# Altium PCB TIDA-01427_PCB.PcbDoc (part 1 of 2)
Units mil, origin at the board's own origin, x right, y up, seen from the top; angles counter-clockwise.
Board outline 1968.5 x 3149.61 mil, 4 copper layers (Top Layer, GND, PWR, Bottom Layer), stack 61.6 mil thick; 174 components, 73 nets, 411 pads, 102 vias.
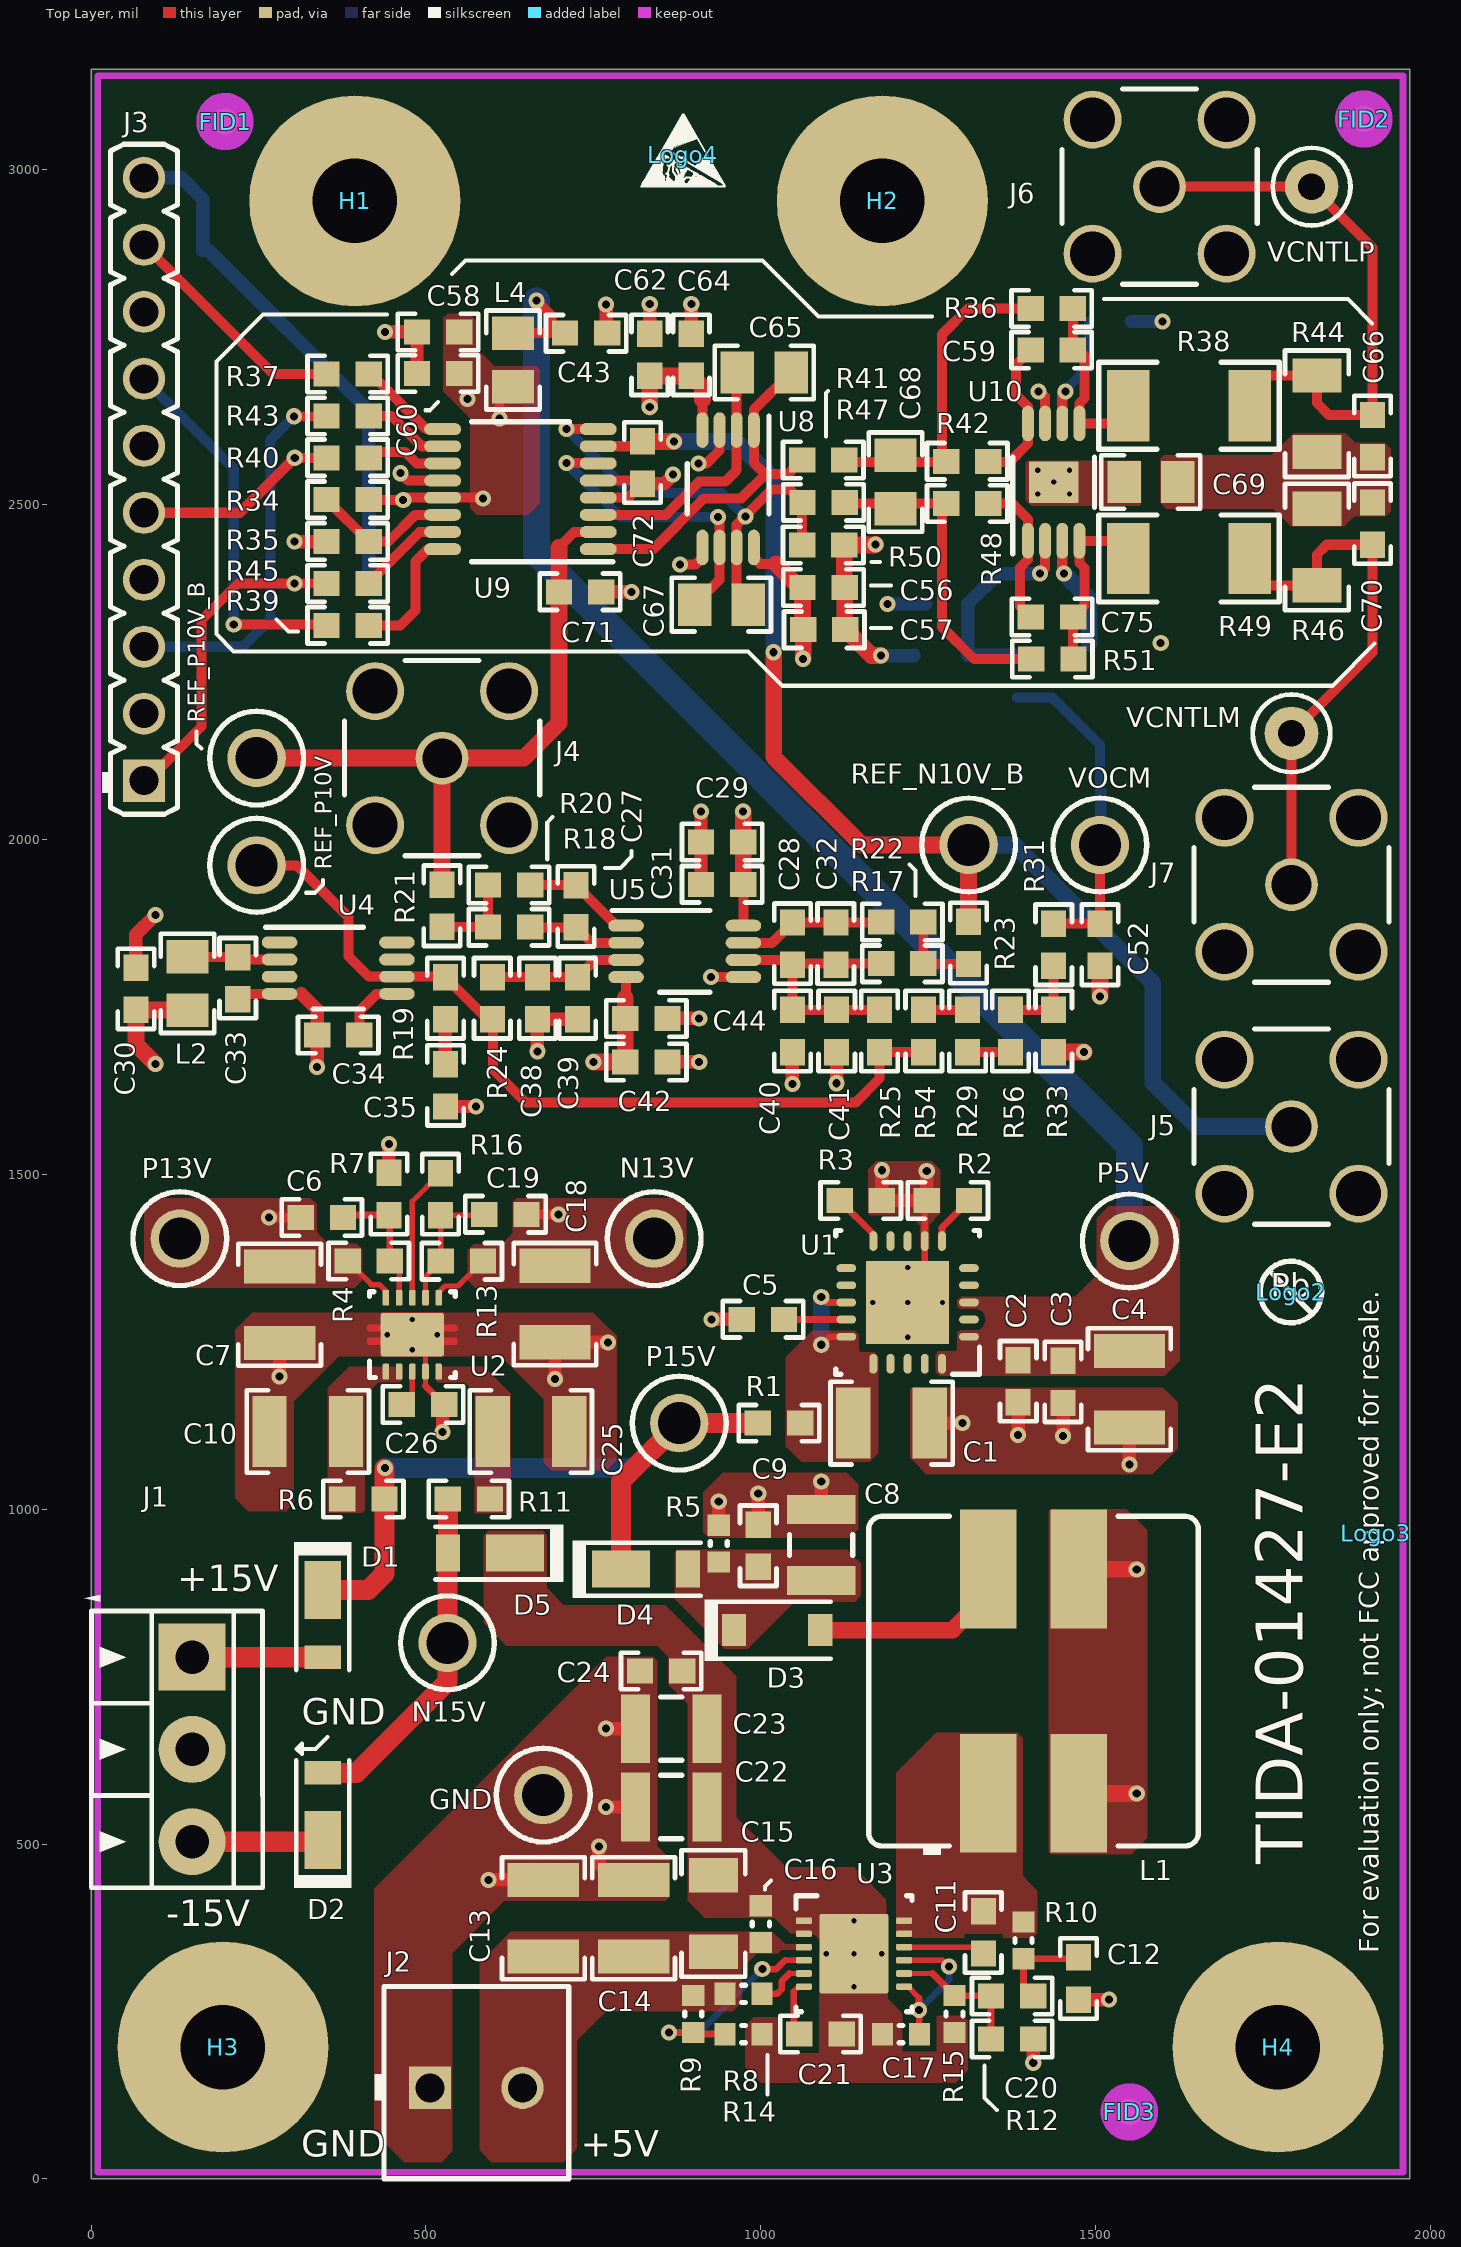
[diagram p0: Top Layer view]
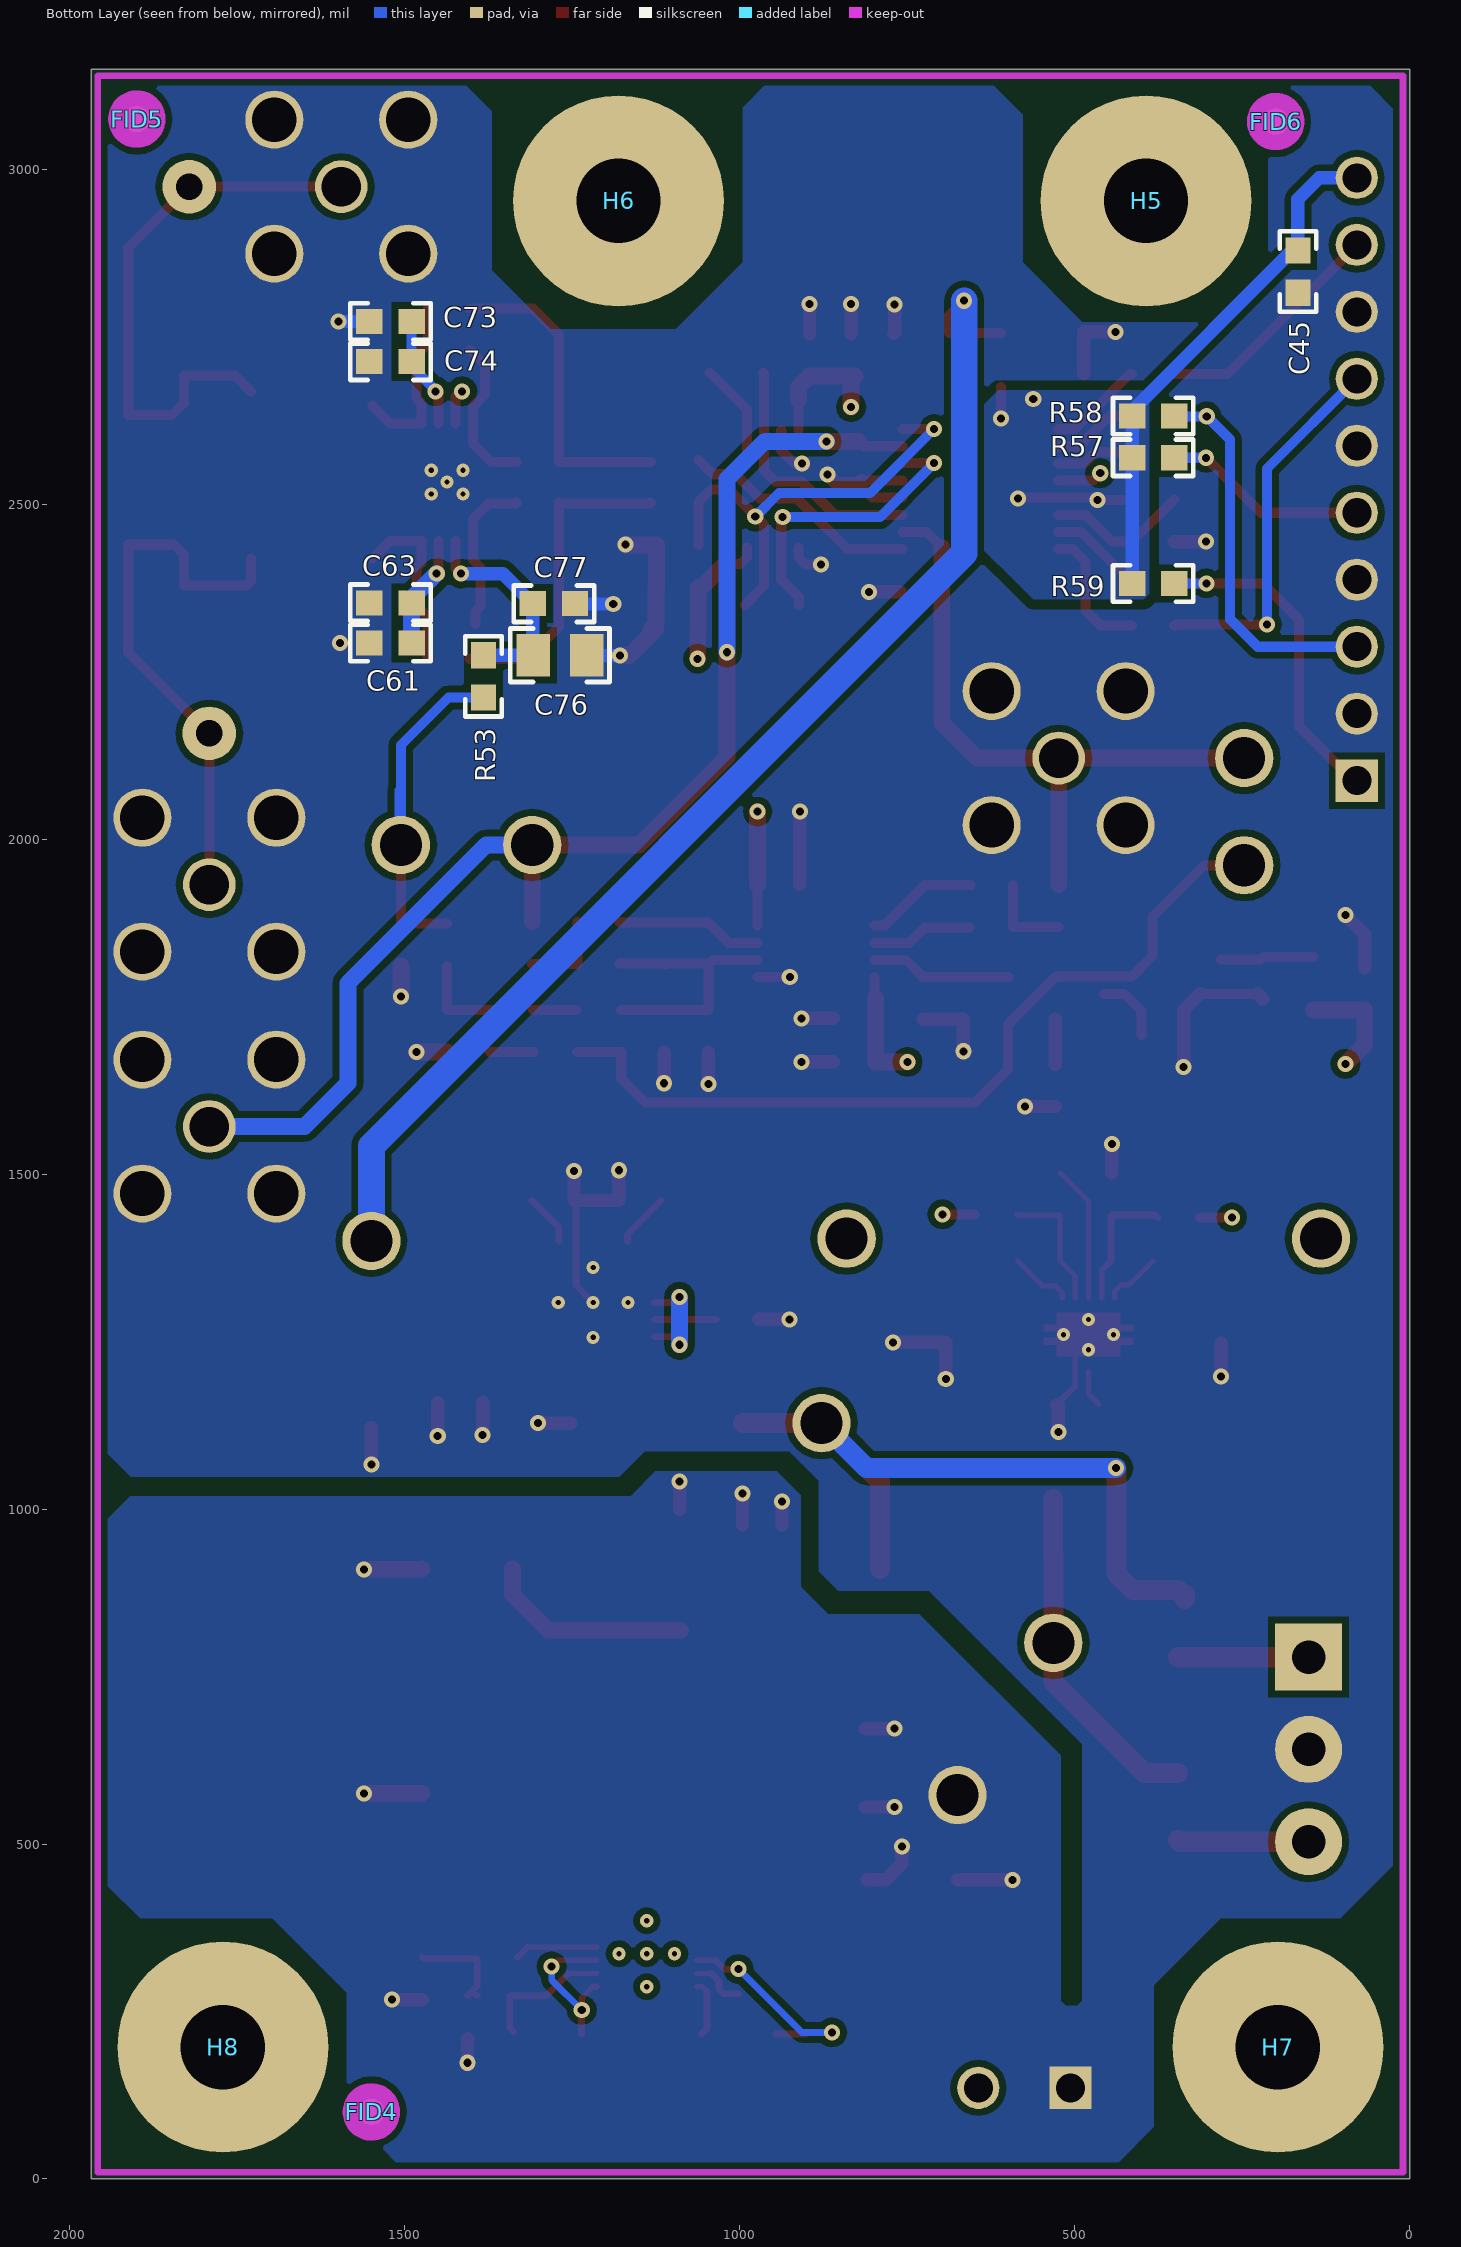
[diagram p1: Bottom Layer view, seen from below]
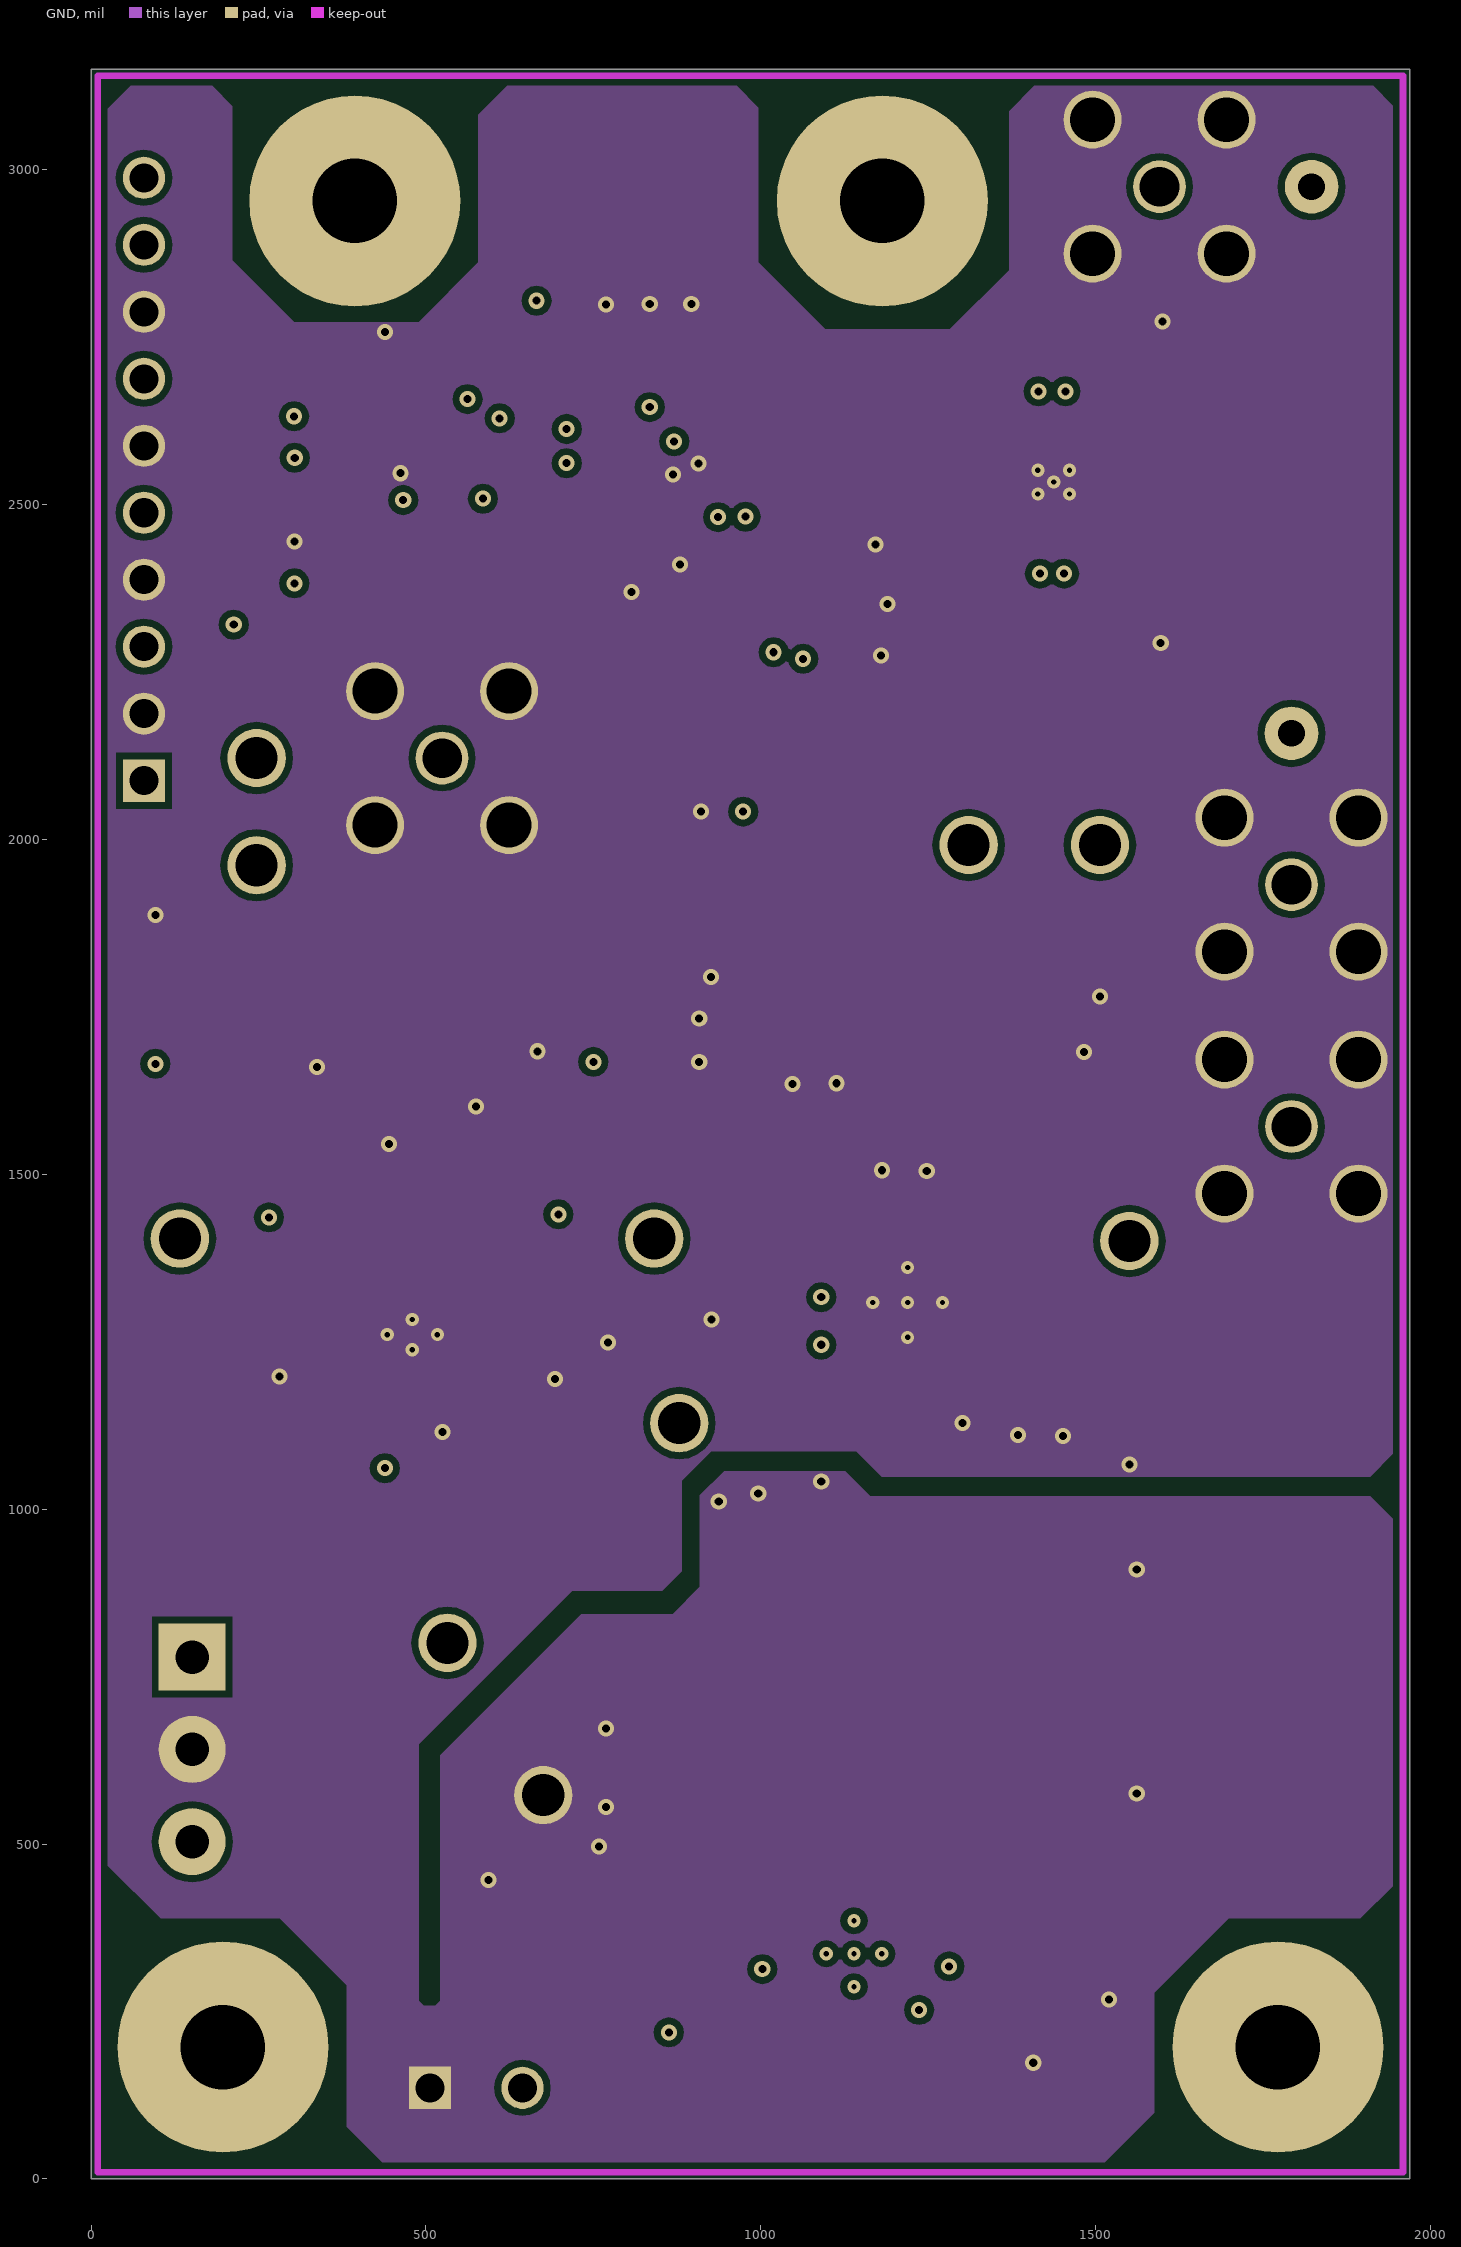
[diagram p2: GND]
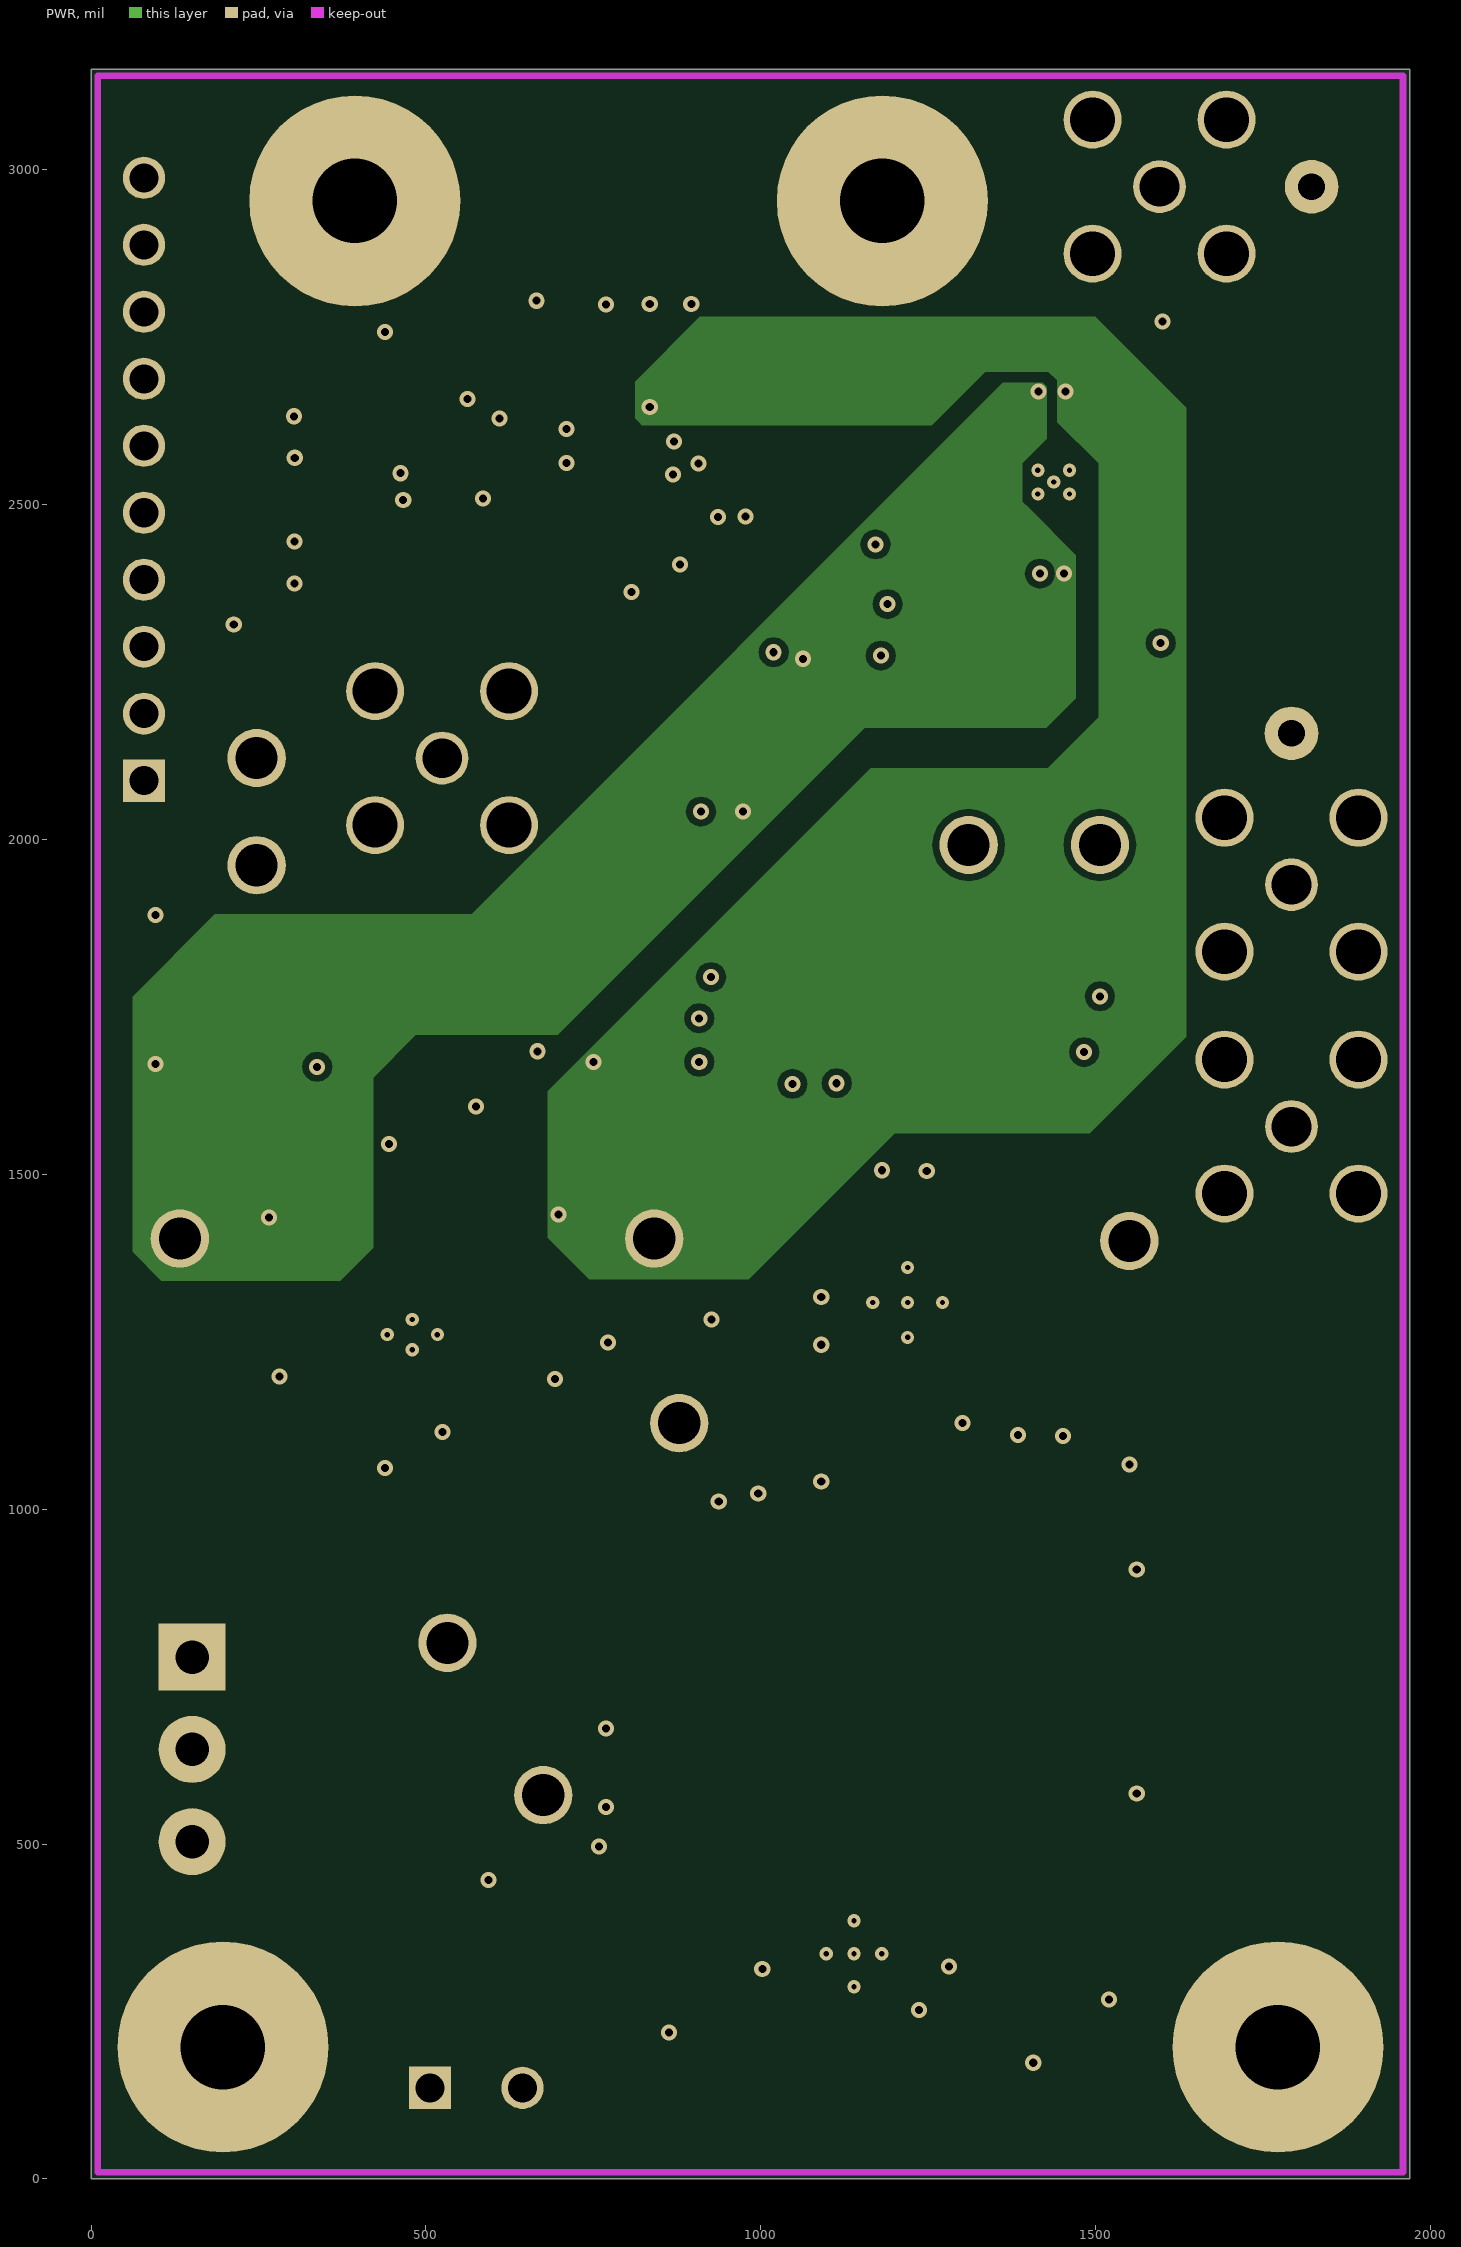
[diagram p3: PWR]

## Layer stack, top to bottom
Top Solder: solder mask 0.4, Solder Resist, Dk 3.5
Top Layer: signal copper 1.4
Dielectric 1: dielectric 10, FR-4 High Tg, Dk 4.2
GND: signal copper 1.4
Dielectric 2: dielectric 36, FR-4 High Tg, Dk 4.2
PWR: signal copper 1.4
Dielectric3: core 10, FR-4 High Tg, Dk 4.8
Bottom Layer: signal copper 1.4
Bottom Solder: solder mask 0.4, Solder Resist, Dk 3.5

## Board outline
0,0 1968.5,0 1968.5,3149.61 0,3149.61

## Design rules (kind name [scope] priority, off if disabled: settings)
AcuteAngle [All] p1: minimum=4.50000000000000E+0001 checktracksonly=FALSE
AssemblyTestPointUsage [All] p1: valid=2
Clearance Clearance_Keepouts [((IsTrack Or IsArc) And Not InPoly) And IsFree and IsKeepOut vs ((IsTrack Or IsArc) And Not InPoly) And IsFree and IsKeepOut] p1: gap=0
Clearance Clearance_Poly [InPolygon] p2: gap=10 except(15: Poly-Poly)
Clearance [All] p3: gap=7.87
ComponentClearance ComponentClearance_MountingHoles_FiducialMarks [InComponentClass('Mounting Holes') vs InComponentClass('FiducialMark')] p1: gap=10 collisioncheckmode=3 verticalgap=10 showdistances=FALSE
ComponentClearance ComponentClearance_Shunt [InComponentClass('Header') vs InComponentClass('Shunt')] p2: gap=0 collisioncheckmode=3 verticalgap=0 showdistances=FALSE
ComponentClearance ComponentClearance_Logo [InComponentClass('Logo')] p3: gap=10 collisioncheckmode=3 verticalgap=10 showdistances=FALSE
ComponentClearance ComponentClearance_ScrewToNut [(HasFootprint('NY PMS 440 0025 PH')) vs (HasFootprint('Keystone_1902C'))] p4: gap=5 collisioncheckmode=3 verticalgap=10 showdistances=FALSE
ComponentClearance ComponentClearance_MountingHoles [InComponentClass('Mounting Holes')] p5: gap=10 collisioncheckmode=3 verticalgap=100000 showdistances=FALSE
ComponentClearance ComponentClearance_SmallPassives [HasFootprint('0201*') or HasFootprint('0402*') or HasFootprint('0508') or HasFootprint('0603*') or HasFootprint('0612') or HasFootprint('0805*') or HasFootprint('0815*') or HasFootprint('0830*') or HasFootprint('1206*') or HasFootprint('1210*') or HasFootprint('1808*') or HasFootprint('1812*') or HasFootprint('1825*') or HasFootprint('2010*') or HasFootprint('2220*') or HasFootprint('2225*') or HasFootprint('2512*') or HasFootprint('2728*') or HasFootprint('3518*') vs HasFootprint('0201*') or HasFootprint('0402*') or HasFootprint('0508') or HasFootprint('0603*') or HasFootprint('0612') or HasFootprint('0805*') or HasFootprint('0815*') or HasFootprint('0830*') or HasFootprint('1206*') or HasFootprint('1210*') or HasFootprint('1808*') or HasFootprint('1812*') or HasFootprint('1825*') or HasFootprint('2010*') or HasFootprint('2220*') or HasFootprint('2225*') or HasFootprint('2512*') or HasFootprint('2728*') or HasFootprint('3518*')] p6: gap=10 collisioncheckmode=3 verticalgap=10 showdistances=FALSE
ComponentClearance ComponentClearance_THtoSMT [IsThruComponent vs IsSMTComponent] p7: gap=10 collisioncheckmode=3 verticalgap=10 showdistances=FALSE
ComponentClearance ComponentClearance_THtoTH [IsThruComponent vs IsThruComponent] p8: gap=10 collisioncheckmode=3 verticalgap=10 showdistances=FALSE
ComponentClearance [All] p9: gap=10 collisioncheckmode=3 verticalgap=10 showdistances=FALSE
DiffPairsRouting [All] p1: maxlimit=100 minlimit=10 mostfreqgap=10 toplayer_minwidth=15 toplayer_maxwidth=15 toplayer_prefwidth=15 midlayer1_minwidth=15 midlayer1_maxwidth=15 midlayer1_prefwidth=15 midlayer2_minwidth=15 midlayer2_maxwidth=15 midlayer2_prefwidth=15 bottomlayer_minwidth=15 bottomlayer_maxwidth=15 bottomlayer_prefwidth=15 maxuncoupledlength=1000
FabricationTestPointUsage TestPointUsage [All] p1: valid=2 allowmultiple=FALSE
FabricationTestpoint Testpoint [All] p1: side=3 testpointundercomponent=TRUE minsize=40 maxsize=100 preferedsize=60 minholesize=0 maxholesize=40 preferedholesize=32 testpointgrid=1 allowsidetop=TRUE allowsidebottom=TRUE usegrid=TRUE gridtolerance=0.01
FanoutControl Fanout_LCC [IsLCC] p1: bgadir=Out bgaviamode=Centered fanoutstyle=Auto fanoutdirection=Alternating viagrid=1 // Fanout_LCC (Default Rule)
FanoutControl Fanout_BGA [IsBGA] p2: bgadir=Out bgaviamode=Centered fanoutstyle=Auto fanoutdirection=Alternating viagrid=1 // Fanout_BGA (Default Rule)
FanoutControl Fanout_Default [All] p4: bgadir=Out bgaviamode=Centered fanoutstyle=Auto fanoutdirection=Alternating viagrid=1 // Fanout_Default (Default Rule)
FanoutControl Fanout_Small [(CompPinCount < 5)] p5: bgadir=Out bgaviamode=Centered fanoutstyle=Auto fanoutdirection=OutThenIn viagrid=1 // Fanout_Small (Default Rule)
HoleSize [All] p1: absolutevalues=TRUE maxlimit=251 minlimit=7.87 maxpercent=80.000 minpercent=20.000
MinimumAnnularRing MinimumAnnularRing_ThermalPadVias [IsVia and InAnyComponent] p1: minimumring=5.91
MinimumAnnularRing [All] p2: minimumring=6
MinimumSolderMaskSliver MinimumSolderMaskSliver_Logo [InComponentClass('Logo') vs InComponentClass('Logo')] p1: minsoldermaskwidth=0.7
MinimumSolderMaskSliver [All] p2: minsoldermaskwidth=3.94
PlaneConnect [All] p1: planeconnectstyle=Relief reliefexpansion=10 reliefentries=4 reliefconductorwidth=10 reliefairgap=10
PolygonConnect [All] p1: connectstyle=Direct reliefconductorwidth=10 reliefentries=4 polygonreliefangle="90 Angle" airgapwidth=10
RoutingVias ThermalPadVias [IsVia and InAnyComponent] p1: holewidth=7.87 width=19.68 viastyle="Through Hole" minholewidth=7.87 minwidth=19.68 maxholewidth=12.99 maxwidth=23.62
RoutingVias [All] p2: holewidth=12 width=24 viastyle="Through Hole" minholewidth=10 minwidth=20 maxholewidth=40 maxwidth=65
SilkToBoardRegionClearance [Not ((IsComment or IsDesignator) And (Hide <> 'False')) and not InRegion(1000,500,4000,800)] p1:
SilkToSilkClearance SilkToSilkClearance_Pb-FreeLogo [(HasFootprint('Pb-Free_Overlay_Medium') OR HasFootprint('Pb-Free_Overlay_Small')) vs (HasFootprint('Pb-Free_Overlay_Medium') OR HasFootprint('Pb-Free_Overlay_Small'))] p1: silktosilkclearance=0
SilkToSilkClearance [All] p2: silktosilkclearance=4
SilkToSolderMaskClearance SilkToComponentPadClearance [(IsPad or IsFill or IsRegion) and InAnycomponent] p1: minsilkscreentomaskgap=5 clearancetoexposedcopper=TRUE
SilkToSolderMaskClearance "Silk to Solder Mask Opening" [All] p2: minsilkscreentomaskgap=4 clearancetoexposedcopper=FALSE
SolderMaskExpansion [All] p1: expansion=1.97
Width [All] p1: maxlimit=100 minlimit=6 preferedwidth=10 checkconnectedcopper=TRUE
15 further rules are at their usual default settings.

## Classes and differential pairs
component class "Mounting Holes": H1 H2 H3 H4
component class TIDA-01427_Hardware: FID1 FID2 FID3 FID4 FID5 FID6 H1 H2 H3 H4 H5 H6 H7 H8 Logo2 Logo3 Logo4 ZZ1 ZZ2 ZZ3 ZZ4
component class FiducialMark: FID1 FID2 FID3 FID4 FID5 FID6
component class AssemblyNote: ZZ1 ZZ2 ZZ3 ZZ4
component class Header: J3
component class TIDA-01427_DAC_I2V_Filter_Attenuator: C43 C45 C56 C57 C58 C59 C60 C61 C62 C63 C64 C65 C66 C67 C68 C69 C70 C71 C72 C73 C74 C75 C76 C77 J3 J6 J7 L4 R34 R35 R36 R37 R38 R39 R40 R41 R42 R43 R44 R45 R46 R47 R48 R49 R50 R51 R53 R57 R58 R59 U8 U9 U10 VCNTLM VCNTLP
component class TIDA-01427_Power_Supply: C1 C2 C3 C4 C5 C6 C7 C8 C9 C10 C11 C12 C13 C14 C15 C16 C17 C18 C19 C20 C21 C22 C23 C24 C25 C26 D1 D2 D3 D4 D5 GND J1 J2 L1 N13V N15V P5V P13V P15V R1 R2 R3 R4 R5 R6 R7 R8 R9 R10 R11 R12 R13 R14 R15 R16 U1 U2 U3
component class TIDA-01427_Reference: C27 C28 C29 C30 C31 C32 C33 C34 C35 C38 C39 C40 C41 C42 C44 C52 J4 J5 L2 R17 R18 R19 R20 R21 R22 R23 R24 R25 R29 R31 R33 R54 R56 REF_N10V_B REF_P10V REF_P10V_B U4 U5 VOCM

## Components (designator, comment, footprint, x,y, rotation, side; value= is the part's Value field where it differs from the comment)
C1 "GRM32ER71H106KA12L" 1210_270 1195,1128.26 r0 top
C2 "GCM188R71H104KA57D" 0603 1384,1190.9 r270 top
C3 "GRM188R61H105KAALD" 0603 1451,1189.9 r270 top
C4 "GRM32EC81C476ME15L" 1210_270 1550,1178.9 r270 top
C5 "GRM188R61H105KAALD" 0603 1003,1283.26 r180 top
C6 "C0603C103J5RACTU" 0603 344.58,1435.36 r180 top
C7 "GRM32ER71H106KA12L" 1210_270 281.58,1305 r270 top
C8 "GRM32ER71E226KE15L" 1210L 1090,946.26 r90 top
C9 "GCM188R71H104KA57D" 0603 996,945.26 r90 top
C10 "GRM32ER71H106KA12L" 1210_270 323.58,1115.74 r180 top
C11 "C0603C103J5RACTU" 0603 1332,368 r90 top
C12 "C0603C103J5RACTU" 0603 1474,299.26 r270 top
C13 "GRM32ER71H106KA12L" 1210_270 675.1,389.26 r90 top
C14 "GRM32ER71H106KA12L" 1210_270 810.1,389.26 r90 top
C15 "GRM319R61E475KA12D" 1206 929,396.26 r90 top
C16 "C1608X7R1H104K" 0603L 1000,380.26 r90 top
C17 "C1608X7R1E105K080AB" 0603L 1208.9,216.26 r0 top
C18 "GRM32ER71H106KA12L" 1210_270 692.58,1306 r270 top
C19 "C0603C103J5RACTU" 0603 618.58,1440 r0 top
C20 "GRM188R71H102JA01D" 0603 1375,273.26 r180 top
C21 "C0603C103J5RACTU" 0603 1088.9,216.26 r0 top
C22 "GRM32ER71E226KE15L" 1210L 866,555.26 r0 top
C23 "" 1210L 866,672.26 r0 top
C24 "GCM188R71H104KA57D" 0603 851,758.26 r0 top
C25 "GRM32ER71H106KA12L" 1210_270 656.58,1115.74 r0 top
C26 "C0603C103J5RACTU" 0603 495.58,1156 r180 top
C27 "GRM188R71E105KA12D" 0603 724,1899.76 r90 top
C28 "GRM188R71E105KA12D" 0603 1047,1844.09 r90 top
C29 "C1608X5R1E106M080AC" 0603 942,1995.64 r180 top
C30 "GRM188R71E105KA12D" 0603 67,1776.64 r90 top
C31 "C0603C104J3RACTU" 0603 942,1932.64 r0 top
C32 "C1608X5R1E106M080AC" 0603 1111.77,1844.09 r90 top
C33 "GRM188R71E105KA12D" 0603 219,1792.5 r270 top
C34 "GRM188R71E105KA12D" 0603 369,1707.5 r180 top
C35 "C1608X5R1E106M080AC" 0603 529,1632.5 r90 top
C38 "C1608X5R1E106M080AC" 0603 666.27,1762.5 r270 top
C39 "C0603C104J3RACTU" 0603 726.27,1762.5 r270 top
C40 "C1608X5R1E106M080AC" 0603 1047,1713.64 r270 top
C41 "C0603C104J3RACTU" 0603 1113,1713.64 r270 top
C42 "C1608X5R1E106M080AC" 0603 829,1667.5 r0 top
C43 "GRM188R71E105KA12D" 0603 739,2755.26 r0 top
C44 "C0603C104J3RACTU" 0603 829,1732.5 r180 top
C45 "GRM188R71E105KA12D" 0603 167,2847.26 r270 bottom
C52 "GRM188R71E105KA12D" 0603 1506,1842.38 r90 top
C56 "C1608X5R1E106M080AC" 0603 1093.5,2375.76 r0 top
C57 "C0603C104J3RACTU" 0603 1094.5,2312.76 r180 top
C58 "C1608X5R1E106M080AC" 0603 518,2757.26 r180 top
C59 "C0603C751J5GACTU" 0603 1434,2730 r180 top
C60 "C0603C104J3RACTU" 0603 518,2695.26 r0 top
C61 "C1608X5R1E106M080AC" 0603 1521.5,2292.76 r0 bottom
C62 "C1608X5R1E106M080AC" 0603 834,2723 r90 top
C63 "C0603C104J3RACTU" 0603 1521.5,2352.76 r180 bottom
C64 "C0603C104J3RACTU" 0603 896,2723 r270 top
C65 "GQM2195C1H200JB01D" 0805_HV 1005,2696.76 r180 top
C66 "GRM188R71H103KA01D" 0603 1913,2601.77 r270 top
C67 "GQM2195C1H200JB01D" 0805_HV 941,2350 r180 top
C68 "08055A152JAT2A" 0805_HV 1201,2533 r270 top
C69 "0805YD106KAT2A" 0805_HV 1582,2533 r180 top
C70 "GRM188R71H103KA01D" 0603 1913,2471 r270 top
C71 "06035A151JAT2A" 0603 730,2369.26 r0 top
C72 "06035A151JAT2A" 0603 823,2562.26 r270 top
C73 "C1608X5R1E106M080AC" 0603 1521.5,2772.76 r0 bottom
C74 "C0603C104J3RACTU" 0603 1521.5,2712.76 r180 bottom
C75 "C0603C751J5GACTU" 0603 1434.5,2331.49 r180 top
C76 "0805YD106KAT2A" 0805_HV 1268.5,2274.49 r180 bottom
C77 "C0603C104J3RACTU" 0603 1277.5,2351.49 r180 bottom
D1 "DFLS130L-7" PowerDI123 345.9,829 r270 top
D2 "DFLS130L-7" PowerDI123 345.9,556 r90 top
D3 "RB160M-60TR" SOD-123 1024,819.26 r0 top
D4 "DFLS130L-7" PowerDI123 841,910.26 r0 top
D5 "DFLS130L-7" PowerDI123 583,934.26 r180 top
FID1 "Fiducial" Fiducial10-20 200,3071.26 r180 top
FID2 "Fiducial" Fiducial10-20 1900,3075 r0 top
FID3 "Fiducial" Fiducial10-20 1550,100 r90 top
FID4 "Fiducial" Fiducial10-20 1550,100 r90 bottom
FID5 "Fiducial" Fiducial10-20 1900,3075 r90 bottom
FID6 "Fiducial" Fiducial10-20 200,3071.26 r90 bottom
GND "5007" Keystone5007 675,573 r90 top
H1 "NY PMS 440 0025 PH" "NY PMS 440 0025 PH" 393.7,2952.76 r0 top
H2 "NY PMS 440 0025 PH" "NY PMS 440 0025 PH" 1181.1,2952.76 r0 top locked
H3 "NY PMS 440 0025 PH" "NY PMS 440 0025 PH" 196.85,196.85 r0 top locked
H4 "NY PMS 440 0025 PH" "NY PMS 440 0025 PH" 1771.65,196.85 r0 top
H5 "1902C" Keystone_1902C 393.7,2952.76 r180 bottom locked
H6 "1902C" Keystone_1902C 1181.1,2952.76 r180 bottom
H7 "1902C" Keystone_1902C 196.85,196.85 r180 bottom locked
H8 "1902C" Keystone_1902C 1771.65,196.85 r180 bottom locked
J1 "ED555/3DS" TERM_BLK_ED555-3DS 151,779 r270 top
J2 "39357-0002" Molex_39357-0002 575.1,136 r0 top
J3 "61301011121" Wurth_61301011121 79,2537.26 r90 top
J4 "901-144-8RFX" Amphenol_901-144-8RFX 524,2121 r0 top
J5 "901-144-8RFX" Amphenol_901-144-8RFX 1792,1571 r0 top
J6 "901-144-8RFX" Amphenol_901-144-8RFX 1595,2974 r0 top
J7 "901-144-8RFX" Amphenol_901-144-8RFX 1792,1932 r0 top
L1 "SRF1260-101M" SRF1260 1406.9,743.13 r90 top
L2 "MPZ2012S102AT000" 0805_HV 144,1784.64 r270 top
L4 "MPZ2012S102AT000" 0805_HV 630,2715.26 r90 top
Logo2 "Pb-Free Symbol" Pb-Free_Overlay_Small 1791,1324 r0 top
Logo3 "FCC disclaimer" FCC_disclaimer 1918,964 r90 top
Logo4 "ESD Susceptible" ESD_Overlay_Small 883,3022 r0 top
N13V "5007" Keystone5007 840.58,1403.74 r0 top
N15V "5007" Keystone5007 532,800.26 r90 top
P5V "5007" Keystone5007 1550,1400.26 r0 top
P13V "5007" Keystone5007 132.58,1403.74 r0 top
P15V "5007" Keystone5007 878,1128.26 r90 top
R1 "CRCW06030000Z0EA" 0603 1027,1128.26 r180 top
R2 "CRCW06030000Z0EA" 0603 1279,1460.62 r0 top
R3 "CRCW06030000Z0EA" 0603 1149,1460.62 r180 top
R4 "CRCW0603102KFKEA" 0603 414.58,1370.36 r180 top
R5 "CRCW06033K01FKEA" 0603L 937,948.26 r270 top
R6 "CRCW06030000Z0EA" 0603 406.5,1015 r0 top
R7 "RC0603FR-0710K2L" 0603 444.58,1470.36 r270 top
R8 "CRCW0603768KFKEA" 0603L 973.9,276.26 r0 top
R9 "CRCW060349K9FKEA" 0603L 898.9,246.26 r90 top
R10 "CRCW060320K0FKEA" 0603L 1392,356.26 r270 top
R11 "CRCW06030000Z0EA" 0603 564,1015 r180 top
R12 "CRCW0603137KFKEA" 0603 1375,209 r0 top
R13 "CRCW0603115KFKEA" 0603 553.58,1370 r0 top
R14 "CRCW060322K6FKEA" 0603L 973.9,216.26 r180 top
R15 "CRCW060320K0FKEA" 0603L 1288.9,246.26 r90 top
R16 "RC0603FR-0710K5L" 0603 521.58,1470 r270 top
R17 "RT0603DRE071KL" 0603 1211,1814.09 r0 top
R18 "CRCW06030000Z0EA" 0603 624,1868.64 r180 top
R19 "CRCW06031R00FKEA" 0603 529,1762.5 r90 top
R20 "CRCW06030000Z0EA" 0603 624,1931.64 r180 top
R21 "CRCW06030000Z0EA" 0603 524,1900.64 r90 top
R22 "CRCW06030000Z0EA" 0603 1211,1876.09 r0 top
R23 "CRCW06030000Z0EA" 0603 1310,1845.09 r90 top
R24 "RT0603DRE071KL" 0603 599,1762.5 r90 top
R25 "RT0603DRE071KL" 0603 1177,1713.64 r90 top
R29 "RT0603DRE074K02L" 0603 1308.38,1713.64 r90 top
R31 "CRCW06030000Z0EA" 0603 1437,1842.38 r90 top
R33 "RT0603DRE07374RL" 0603 1437,1713.64 r90 top
R34 "CRCW06030000Z0EA" 0603 383,2506.76 r0 top
R35 "CRCW06030000Z0EA" 0603 383,2444.26 r0 top
R36 "RT0603DRE071KL" 0603 1434,2792 r0 top
R37 "CRCW06030000Z0EA" 0603 383,2694.26 r0 top
R38 "CRCW2010348RFKEF" 2010 1639,2647 r0 top
R39 "CRCW06030000Z0EA" 0603 383,2319.26 r0 top
R40 "CRCW06030000Z0EA" 0603 383,2569.26 r0 top
R41 "RT0603DRE071KL" 0603 1093,2566 r0 top
R42 "RT0603DRE07499RL" 0603 1308,2564 r0 top
R43 "CRCW06030000Z0EA" 0603 383,2631.76 r0 top
R44 "RT1206DRD0728RL" 1206 1830,2635 r90 top
R45 "CRCW06030000Z0EA" 0603 383,2381.76 r0 top
R46 "RT1206DRD0728RL" 1206 1830,2436 r90 top
R47 "RT0603DRE071KL" 0603 1093.5,2502.76 r0 top
R48 "RT0603DRE07499RL" 0603 1308,2501 r0 top
R49 "CRCW2010348RFKEF" 2010 1639,2419 r0 top
R50 "CRCW06030000Z0EA" 0603 1093,2439 r180 top
R51 "RT0603DRE071KL" 0603 1435,2269 r0 top
R53 "CRCW06030000Z0EA" 0603 1382.52,2243 r90 bottom
R54 "CRCW06030000Z0EA" 0603 1242.93,1713.64 r270 top
R56 "RT0603DRE07590RL" 0603 1372.62,1713.64 r270 top
R57 "RT0603DRE071KL" 0603 383,2569.33 r0 bottom
R58 "RT0603DRE071KL" 0603 383,2631.83 r0 bottom
R59 "RT0603DRE071KL" 0603 383,2381.83 r0 bottom
REF_N10V_B "5007" Keystone5007 1310,1991.38 r90 top
REF_P10V "5007" Keystone5007 247.2,1961.02 r90 top
REF_P10V_B "5007" Keystone5007 247.2,2121.02 r90 top
U1 "TPS7A4700RGWR" RGW0020A 1219,1308.46 r180 top
U2 "TPS7A3901DSC" DSC0010J 479.58,1260.36 r90 top
U3 "LM5160DNTR" DNT0012B 1138.9,336.26 r0 top
U4 "REF5010AIDGKR" DGK0008A_N 369,1807.5 r0 top
U5 "OPA2209AIDGKR" DGK0008A_N 886.27,1832.5 r0 top
U8 "OPA2209AIDGKR" DGK0008A_N 951,2523.02 r270 top
U9 "DAC8802IPWR" PW0016A_N 641,2522.53 r180 top
U10 "THS4130IDGNR" DGN0008D_N 1437,2533 r90 top
VCNTLM "5001" Keystone5001 1792,2158 r90 top
VCNTLP "5001" Keystone5001 1822,2974 r90 top
VOCM "5007" Keystone5007 1506,1991.38 r0 top
ZZ1 "This Assembly Note is for PCB labels only" AssemblyNoteLabel 184,3699.26 r0 top
ZZ2 "These assemblies are ESD sensitive, ESD precautions shall be observed." AssemblyNote 179,3588.37 r0 top
ZZ3 "These assemblies must be clean and free from flux and all contaminants. Use of no clean flux is not acceptable." AssemblyNote 179,3499.82 r0 top
ZZ4 "These assemblies must comply with workmanship standards IPC-A-610 Class 2, unless otherwise specified." AssemblyNote 179,3411.26 r0 top

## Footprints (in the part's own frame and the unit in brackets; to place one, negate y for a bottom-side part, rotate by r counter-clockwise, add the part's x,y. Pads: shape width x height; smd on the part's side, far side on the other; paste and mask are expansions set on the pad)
0603 [mm] "0603 from SM-752 data"
  rect 1x0.95 smd: 1(-0.8,0) 2(0.8,0)
  silkscreen extent -1.52,-0.69 1.52,0.69, body extent -0.87,-0.47 0.87,0.47, height 1
0603L [mm] "0603 from SM-752 data"
  rect 0.8x0.85 smd: 1(-0.7,0) 2(0.7,0)
  silkscreen extent -0.07,-0.33 0.07,0.33, body extent -0.87,-0.47 0.87,0.47, height 1
0805_HV [mil] "0805 with 30mil clearance between pads"
  rect 50x63 smd: 1(-40,0) 2(40,0)
  silkscreen extent -74,-40 74,40, body extent -43,-29 43,29, height 57
1206 [mm] "1206 from SM-752 data"
  rect 1.3x1.85 smd: 1(-1.45,0) 2(1.45,0)
  silkscreen extent -2.4,-1.21 2.4,1.21, body extent -1.7,-0.9 1.7,0.9, height 1.35
1210_270 [mm] "1210"
  rect 1.3x2.7 smd: 1(-1.45,0) 2(1.45,0)
  silkscreen extent -2.32,-1.57 2.32,1.57, body extent -1.7,-1.35 1.7,1.35, height 2.7
1210L [mm] "1210 from SM-752 data"
  rect 1.1x2.6 smd: 1(-1.35,0) 2(1.35,0)
  silkscreen extent -0.4,-1.2 0.4,1.2, body extent -1.7,-1.35 1.7,1.35, height 1.35
2010 [mm] "Chip Capacitor, Body 5.08x2.54mm, IPC Medium Density"
  rect 1.6x2.7 smd: 1(-2.3,0) 2(2.3,0)
  silkscreen extent -3.42,-1.65 3.42,1.65, body extent -2.73,-1.45 2.73,1.45, height 1.66
Amphenol_901-144-8RFX [mm] "SMA Straight Jack, TH"
  round 2 hole 1.5: 1(0,0)
  round 2.2 hole 1.7: 2(-2.54,2.54) 3(-2.54,-2.54) 4(2.54,-2.54) 5(2.54,2.54)
  silkscreen extent -3.7,-3.7 3.7,3.7, body extent -3.7,-3.7 3.7,3.7, height 9.93
AssemblyNote [mil] "Assembly Note"
AssemblyNoteLabel [mil] "Assembly Note for PCB Labels"
DGK0008A_N [mm] "TSOP, 8-Leads, Body 3x3mm, Pitch 0.65mm, IPC Medium Density"
  oval 1.35x0.45 smd: 1(-2.225,0.975) 2(-2.225,0.325) 3(-2.225,-0.325) 4(-2.225,-0.975) 5(2.225,-0.975) 6(2.225,-0.325) 7(2.225,0.325) 8(2.225,0.975)
  silkscreen extent -2.75,-1.55 0.95,1.55, body extent -2.45,-1.5 2.45,1.5, height 0.96
DGN0008D_N [mm] "TSOP, 8-Leads, Body 3x3mm, Pitch 0.65mm, Thermal Pad 1.89x1.57mm, IPC Medium Density"
  rrect100% 1.35x0.45 smd: 1(-2.225,0.975) 2(-2.225,0.325) 3(-2.225,-0.325) 4(-2.225,-0.975) 5(2.225,-0.975) 6(2.225,-0.325) 7(2.225,0.325) 8(2.225,0.975)
  rrect6% 1.57x1.89 smd: 9(0,0)
  silkscreen extent -2.73,-1.55 0.95,1.55, body extent -2.46,-1.5 2.46,1.5, height 1.1
DNT0012B [mm] "SON, 12-Leads, Body 4x4mm, Pitch 0.5mm"
  rrect40% 0.6x0.25 smd: 1(-1.9,1.25) 2(-1.9,0.75) 3(-1.9,0.25) 4(-1.9,-0.25) 5(-1.9,-0.75) 6(-1.9,-1.25) 7(1.9,-1.25) 8(1.9,-0.75) 9(1.9,-0.25) 10(1.9,0.25) 11(1.9,0.75) 12(1.9,1.25)
  rrect4% 2.6x3 smd paste-1.3: 13(0,0)
  silkscreen extent -2.2,-2.2 2.2,2.2, body extent -2,-2 2,2, height 0.81
DSC0010J [mm] "SON, 10-Leads, Body 3x3mm, Pitch 0.5mm, Thermal Pad 2.4x1.65mm, TI Recommended"
  rrect40% 0.6x0.25 smd: 1(-1.4,1) 2(-1.4,0.5) 3(-1.4,0) 4(-1.4,-0.5) 5(-1.4,-1) 6(1.4,-1) 7(1.4,-0.5) 8(1.4,0) 9(1.4,0.5) 10(1.4,1)
  rrect40% 0.25x0.34 on Top Paste: 11(-0.25,1.53) 11(-0.25,-1.53) 11(0.25,1.53) 11(0.25,-1.53)
  rrect9% 1.5x1.06 on Top Paste: 11(0,0.63) 11(0,-0.63)
  rrect12% 1.65x2.4 smd paste-1 mask-2: 11(0,0)
  Top Layer region: -0.775,-1.2 -0.375,-1.2 -0.375,-1.65 -0.371,-1.669 -0.36,-1.685 -0.344,-1.696 -0.325,-1.7 -0.325,-1.7 -0.325,-1.7 -0.175,-1.7 -0.175,-1.7 -0.156,-1.696 -0.14,-1.685 -0.129,-1.669 -0.125,-1.65 -0.125,-1.65 -0.125,-1.65 -0.125,-1.2 0.125,-1.2 0.125,-1.65 0.129,-1.669 0.14,-1.685 0.156,-1.696 0.175,-1.7 0.175,-1.7 0.175,-1.7 0.325,-1.7 0.325,-1.7 0.344,-1.696 0.36,-1.685 0.371,-1.669 0.375,-1.65 0.375,-1.65 0.375,-1.2 0.775,-1.2 0.794,-1.196 0.81,-1.185 0.821,-1.169 0.825,-1.15 0.825,-1.15 0.825,1.15 0.821,1.169 0.81,1.185 0.794,1.196 0.775,1.2 0.775,1.2 0.375,1.2 0.375,1.65 0.371,1.669 0.36,1.685 0.344,1.696 0.325,1.7 0.325,1.7 0.175,1.7 0.156,1.696 0.14,1.685 0.129,1.669 0.125,1.65 0.125,1.65 0.125,1.2 -0.125,1.2 -0.125,1.65 -0.125,1.65 -0.129,1.669 -0.14,1.685 -0.156,1.696 -0.175,1.7 -0.175,1.7 -0.325,1.7 -0.344,1.696 -0.36,1.685 -0.371,1.669 -0.375,1.65 -0.375,1.65 -0.375,1.2 -0.775,1.2 -0.794,1.196 -0.81,1.185 -0.821,1.169 -0.825,1.15 -0.825,1.15 -0.825,-1.15 -0.821,-1.169 -0.81,-1.185 -0.794,-1.196 -0.775,-1.2
  silkscreen extent -1.63,-1.63 1.63,1.63, body extent -1.5,-1.5 1.5,1.5, height 0.81
ESD_Overlay_Small [mil]
  silkscreen extent -62,-48 64,61
FCC_disclaimer [mil]
Fiducial10-20 [mm]
  round 1 smd mask+0.5: 1(0,0)
  Top Layer keep-out circle w1.178: c0,0 r0.5
Keystone5001 [mil] "For Keystone 500x miniature loop terminals"
  round 80 hole 40: 1(0,0)
  silkscreen extent -58,-58 58,58, body extent -49,-49 49,49, height 182
Keystone5007 [mil] "Keystone Compact loops"
  round 87 hole 63: 1(0,0)
  silkscreen extent -70,-70 70,70, body extent -63,-63 62,63, height 225
Keystone_1902C [mil] "Hex Standoff, 4-40 threaded, nylon"
  body extent -145,-126 146,126, height 501
Molex_39357-0002 [mm] "Terminal Block, 3.5 mm, 2x1, TH"
  rect 1.6x1.6 hole 1.1: 1(-1.75,0)
  round 1.6 hole 1.1: 2(1.75,0)
  silkscreen extent -3.86,-3.45 3.5,3.84, body extent -3.55,-3.45 3.56,3.84, height 8.51
"NY PMS 440 0025 PH" [mm] "4-40 nylon screw and mounting hole"
  round 8 hole 3.2: 1(0,0)
  body extent -3.3,-3.3 3.3,3.3, height 2.69
Pb-Free_Overlay_Small [mil]
  silkscreen extent -46,-46 46,46
PowerDI123 [mm] "Diodes Inc recommended land pattern, document number DS30628 Rev. 6-2"
  rect 2.2x1.4 smd: 1(-1.275,0)
  rect 0.9x1.4 smd: 2(1.275,0)
  silkscreen extent -3.1,-1.09 1.76,1.09, body extent -2.38,-0.97 1.52,0.96, height 1
PW0016A_N [mm] "TSOP, 16-Leads, Body 5x4.4mm, Pitch 0.65mm, IPC Medium Density"
  oval 1.4x0.45 smd: 1(-2.95,2.275) 2(-2.95,1.625) 3(-2.95,0.975) 4(-2.95,0.325) 5(-2.95,-0.325) 6(-2.95,-0.975) 7(-2.95,-1.625) 8(-2.95,-2.275) 9(2.95,-2.275) 10(2.95,-1.625) 11(2.95,-0.975) 12(2.95,-0.325) 13(2.95,0.325) 14(2.95,0.975) 15(2.95,1.625) 16(2.95,2.275)
  silkscreen extent -3.5,-2.55 1.85,2.75, body extent -3.21,-2.5 3.21,2.5, height 1
RGW0020A [mm] "QFN, 20-Leads, Body 5x5mm, Pitch 0.65mm, Thermal Pad 3.15x3.15mm, TI Recommended"
  oval 0.75x0.3 smd: 1(-2.325,1.3) 2(-2.325,0.65) 3(-2.325,0) 4(-2.325,-0.65) 5(-2.325,-1.3) 11(2.325,-1.3) 12(2.325,-0.65) 13(2.325,0) 14(2.325,0.65) 15(2.325,1.3)
  oval 0.3x0.75 smd: 6(-1.3,-2.325) 7(-0.65,-2.325) 8(0,-2.325) 9(0.65,-2.325) 10(1.3,-2.325) 16(1.3,2.325) 17(0.65,2.325) 18(0,2.325) 19(-0.65,2.325) 20(-1.3,2.325)
  rect 3.15x3.15 smd paste-1.575: 21(0,0)
  silkscreen extent -2.73,-2.73 2.73,2.73, body extent -2.58,-2.57 2.57,2.58, height 1.01
SOD-123 [mm] "On Semi recommended land pattern"
  rect 0.915x1.22 smd: 1(-1.637,0) 2(1.637,0)
  silkscreen extent -2.74,-1.17 2.03,1.17, body extent -1.93,-0.9 1.93,0.9, height 1.35
SRF1260 [mm] "SMD, 4-Leads, Body 12.5x12.5mm"
  rect 4.5x2.15 smd: 1(-4.25,1.715) 2(-4.25,-1.715) 3(4.25,-1.715) 4(4.25,1.715)
  silkscreen extent -6.6,-6.25 6.25,6.25, body extent -6.25,-6.25 6.25,6.25, height 6
TERM_BLK_ED555-3DS [mm]
  rect 2.54x2.54 hole 1.27: 1(0,0)
  round 2.54 hole 1.27: 2(3.5,0) 3(7,0)
  silkscreen extent -2.36,-4.09 8.75,2.67, body extent -1.75,-3.83 8.75,2.67, height 8.2
Wurth_61301011121 [mm] "Header, 2.54mm, 10x1, TH"
  rect 1.6x1.6 hole 1.1: 1(-11.43,0)
  round 1.6 hole 1.1: 2(-8.89,0) 3(-6.35,0) 4(-3.81,0) 5(-1.27,0) 6(1.27,0) 7(3.81,0) 8(6.35,0) 9(8.89,0) 10(11.43,0)
  silkscreen extent -12.7,-1.27 12.7,1.6, body extent -12.7,-1.27 12.7,1.27, height 8.54

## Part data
C1 C7 C10 C13 C14 C18 C25: "CAP, CERM, 10 µF, 50 V, +/- 10%, X7R, 1210"
C2 C9 C24: "CAP, CERM, 0.1 µF, 50 V, +/- 10%, X7R, 0603"
C3 C5: "CAP, CERM, 1 µF, 50 V, +/- 10%, X5R, 0603"
C4: "CAP, CERM, 47 µF, 16 V, +/- 20%, X6S, 1210"
C6 C11 C12 C19 C21 C26: "CAP, CERM, 0.01 µF, 50 V, +/- 5%, X7R, 0603"
C8 C22: "CAP, CERM, 22uF, 25V, +/-10%, X7R, 1210"
C15: "CAP, CERM, 4.7 µF, 25 V, +/- 10%, X5R, 1206"
C16: "CAP, CERM, 0.1uF, 50V, +/-10%, X7R, 0603"
C17: "CAP, CERM, 1uF, 25V, +/-10%, X7R, 0603"
C20: "CAP, CERM, 1000 pF, 50 V, +/- 5%, X7R, 0603"
C23: library part GRM32ER71E226KE15L, "CAP, CERM, 22uF, 25V, +/-10%, X7R, 1210"
C27 C28 C30 C33 C34 C43 C45 C52: "CAP, CERM, 1 µF, 25 V, +/- 10%, X7R, 0603"
C29 C32 C35 C38 C40 C42 C56 C58 C61 C62 C73: "CAP, CERM, 10 µF, 25 V, +/- 20%, X5R, 0603"
C31 C39 C41 C44 C57 C60 C63 C64 C74 C77: "CAP, CERM, 0.1 µF, 25 V, +/- 5%, X7R, 0603"
C59 C75: "CAP, CERM, 750 pF, 50 V, +/- 5%, C0G/NP0, 0603"
C65 C67: "CAP, CERM, 20 pF, 50 V, +/- 5%, C0G/NP0, 0805"
C66 C70: "CAP, CERM, 0.01 µF, 50 V, +/- 10%, X7R, 0603"
C68: "CAP, CERM, 1500 pF, 50 V, +/- 5%, C0G/NP0, 0805"
C69 C76: "CAP, CERM, 10 µF, 16 V, +/- 10%, X5R, 0805"
C71 C72: "CAP, CERM, 150 pF, 50 V, +/- 5%, C0G/NP0, 0603"
D1 D2 D4 D5: "Diode, Schottky, 30 V, 1 A, PowerDI123"
D3: "Diode, Schottky, 60 V, 1 A, SOD-123"
FID1 FID2 FID3 FID4 FID5 FID6: "Fiducial mark.  There is nothing to buy or mount."
GND N13V N15V P5V P13V P15V REF_N10V_B REF_P10V REF_P10V_B VOCM: "Test Point, Compact, White, TH"
H1 H2 H3 H4: "Machine Screw, Round, #4-40 x 1/4, Nylon, Philips panhead"
H5 H6 H7 H8: "Standoff, Hex, 0.5\"L #4-40 Nylon"
J1: "Terminal Block, 3.5mm Pitch, 3x1, TH"
J2: "Terminal Block, 3.5 mm, 2x1, Tin, TH"
J3: "Header, 2.54mm, 10x1, Gold, TH"
J4 J5 J6 J7: "SMA Straight Jack, Gold, 50 Ohm, TH"
L1: "Inductor, Drum Core, Ferrite, 100 µH, 1.78 A, 0.171 ohm, SMD"
L2 L4: library part UPZ2012E102-1R5TF, "FERRITE BEAD 1 KOHM 0805 1LN"
Logo2: library part Pb-Free
Logo3: library part FCC_disclaimer, "FCC_disclaimer"
Logo4: library part ESD_Susceptible, "ESD Susceptible Symbol"
R1 R2 R3 R6 R11 R18 R20 R21 R22 R23 R31 R34 R35 R37 R39 R40 R43 R45 R50 R53 R54: "RES, 0, 5%, 0.1 W, 0603"
R4: "RES, 102 k, 1%, 0.1 W, 0603"
R5: "RES, 3.01 k, 1%, 0.1 W, 0603"
R7: "RES, 10.2 k, 1%, 0.1 W, 0603"
R8: "RES, 768 k, 1%, 0.1 W, 0603"
R9: "RES, 49.9 k, 1%, 0.1 W, 0603"
R10 R15: "RES, 20.0 k, 1%, 0.1 W, 0603"
R12: "RES, 137 k, 1%, 0.1 W, 0603"
R13: "RES, 115 k, 1%, 0.1 W, 0603"
R14: "RES, 22.6 k, 1%, 0.1 W, 0603"
R16: "RES, 10.5 k, 1%, 0.1 W, 0603"
R17 R24 R25 R36 R41 R47 R51 R57 R58 R59: "RES, 1.00 k, 0.5%, 0.1 W, 0603"
R19: "RES, 1.00, 1%, 0.1 W, 0603"
R29: "RES, 4.02 k, 0.5%, 0.1 W, 0603"
R33: "RES, 374, 0.5%, 0.1 W, 0603"
R38 R49: "RES, 348, 1%, 0.75 W, AEC-Q200 Grade 0, 2010"
R42 R48: "RES, 499, 0.5%, 0.1 W, 0603"
R44 R46: library part CRCW120628R0FKEA, "RES, 28.0, 0.5%, 0.25 W, 1206"
R56: "RES, 590, 0.5%, 0.1 W, 0603"
U1: "36-V, 1-A, 4.17-uVRMS, RF LDO Voltage Regulator, RGW0020A (VQFN-20)"
U2: "Wide-VIN (+/-33 V), 150-mA, Spilt-Rail Output, Positive and Negative LDO Voltage Regulator with Startup Tracking, DSC0010J (WSON-10)"
U3: "Wide Input 65V, 1.5A Synchronous Step-Down DC-DC Converter, DNT0012B"
U4: "Low Noise, Very Low Drift, Precision Voltage Reference, -40 to 125 degC, 8-pin MSOP (DGK), Green (RoHS & no Sb/Br)"
U5 U8: "2.2 nV/rtHz, 18 MHz, Precision, RRO, Operational Amplifier, 4.5 to 36 V, -40 to 125 degC, 8-pin SOP (DGK0008A), Green (RoHS & no Sb/Br)"
U9: "Dual, Serial Input 14-Bit Multiplying Digital-to-Analog Converter, PW0016A (TSSOP-16)"
U10: library part THS4131IDGNR, "Fully Differential Input/Output Low Noise Amplifier, DGN0008D (VSSOP-8)"
VCNTLM VCNTLP: "Test Point, Miniature, Black, TH"
ZZ1: library part AssemblyNoteLabel
ZZ2 ZZ3 ZZ4: library part AssemblyNote

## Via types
v1: diameter 24, hole 12, Top Layer to Bottom Layer, tented both sides, 80 vias
v2: diameter 19.68, hole 7.87, Top Layer to Bottom Layer, 19 vias
v3: diameter 24, hole 12, Top Layer to Bottom Layer, 3 vias

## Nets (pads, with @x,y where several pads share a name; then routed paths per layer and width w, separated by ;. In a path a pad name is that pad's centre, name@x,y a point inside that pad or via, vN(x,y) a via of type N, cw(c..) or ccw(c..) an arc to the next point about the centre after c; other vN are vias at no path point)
GND: C1.2 C2.2 C3.2 C4.2 C5.2 C7.2 C8.2 C9.2 C10.2 C12.2 C13.2 C14.2 C18.2 C22.1 C23.1 C24.1 C25.2 C26.1 C29.2 C30.2 C31.1 C33.2 C34.2 C35.1 C38.2 C39.2 C40.2 C41.2 C42.2 C43.2 C44.1 C45.2 C52.1 C56.2 C57.1 C58.2 C60.1 C61.2 C62.2 C63.1 C64.1 C69.2 C71.2 C72.2 C73.2 C74.1 C76.2 C77.2 GND.1 J1.2 J2.1 J3.2 J3.4 J3.6 J3.8 J4.2 J4.3 J4.4 J4.5 J5.2 J5.3 J5.4 J5.5 J6.2 J6.3 J6.4 J6.5 J7.2 J7.3 J7.4 J7.5 L1.2 L1.3 R2.1 R3.1 R5.1 R7.1 R12.2 R33.1 R35.1 R50.1 U1.7 U1.21 U2.4 U2.11@479.58,1260.36 U4.4 U5.5 U8.3 U8.5 U9.4 U9.5 U9.12 U10.9 | length 3613.5
  Top Layer w8: 499.27,1183.81 U2.4@499.27,1205.24 U2.11@499.27,1240.68
  Top Layer w10: U2.11@479.58,1260.36 U2.11@499.27,1240.68 ; 499.27,1183.81 C26.1@527.08,1156 ; v2(1219,1308.46) 1244.59,1334.05 U1.7@1244.59,1399.99 1244.59,1457.71 R2.1@1247.5,1460.62
  Top Layer w15: C33.2@227.11,1769.11 U4.4@281.4,1769.11 313.53,1769.11 ; v1(462,2546.26) 472.94,2535.32 U9.12@524.86,2535.32 ; U9.4@757.14,2509.73 801.97,2509.73 C72.2@823,2530.76 ; U9.5@757.14,2535.32 C72.2@818.44,2535.32 ; v1(879,2409.76) 902,2409.76 912.61,2420.37 U8.5@912.61,2435.42 ; v1(907,2561) 919,2561 938.2,2580.2 U8.3@938.2,2610.62 ; v1(925.47,1794.11) U5.5@973.86,1794.11
  Top Layer w20: C30.2@67,1808.13 67,1857.64 v1(96,1886.64) ; C33.2@219,1761 C33.2@227.11,1769.11 ; v1(281.58,1198) C7.2@281.58,1247.91 ; v1(304,2444.26) R35.1@351.5,2444.26 ; 313.53,1769.11 337.5,1745.13 C34.2@337.5,1707.5 v1(337.5,1660.13) ; v1(439,2757.26) C58.2@486.5,2757.26 C60.1@486.5,2695.26 ; R7.1@444.58,1501.86 v1(444.58,1545) ; v1(524.58,1115) 524.58,1153.5 C26.1@527.08,1156 ; C35.1@529,1601 v1(574.36,1601) ; v1(593.19,446.35) C13.2@675.1,446.35 ; v1(666.27,1683.37) C38.2@666.27,1731 C39.2@726.27,1731 ; v1(692.58,1194) C18.2@692.58,1248.91 v1(771.67,1248.91) ; v1(758.1,496.26) 758.1,470.26 782.02,446.35 C14.2@810.1,446.35 ; C71.2@761.5,2369.26 v1(807,2369.26) ; v1(769,555.26) C22.1@812.85,555.26 ; v1(769,672.26) C23.1@812.85,672.26 ; v1(769,2798.26) 769,2756.76 C43.2@770.5,2755.26 ; C72.2@818.44,2535.32 C72.2@823,2530.76 855.5,2530.76 v1(869,2544.26) ; C62.2@834,2754.5 v1(834,2799) ; C42.2@860.5,1667.5 v1(907.86,1667.5) ; C44.1@860.5,1732.5 v1(907.86,1732.5) ; C64.1@896,2754.5 v1(896,2799) ; C31.1@910.5,1932.64 C29.2@910.5,1995.64 v1(910.5,2041.14) ; v1(926,1283.26) C5.2@971.5,1283.26 ; R5.1@937,975.82 v1(937,1011.26) ; C9.2@996,976.76 v1(996,1023.26) ; v1(1047,1634.64) C40.2@1047,1682.14 ; C8.2@1090,999.41 v1(1090,1041.26) ; v1(1113,1635.64) C41.2@1113,1682.14 ; C57.1@1133,2313.76 C57.1@1134,2312.76 ; v1(1180.5,1505.76) R3.1@1180.5,1460.62 R2.1@1247.5,1460.62 v1(1247.5,1504.76) ; C1.2@1252.09,1128.26 v1(1301,1128.26) ; v1(1384,1110.26) C2.2@1384,1159.4 ; R12.2@1406.05,209.44 R12.2@1406.5,209 v1(1406.5,173.44) ; v1(1451,1109.26) C3.2@1451,1158.4 ; C12.2@1474,267.76 v1(1519.5,267.76) ; v1(1550,1066.26) C4.2@1550,1121.81
  Top Layer w25: C57.1@1126,2312.76 1164.76,2274 v1(1179,2274) ; C57.1@1133,2313.76 1125,2321.76 C56.2@1125,2375.76 1124.5,2376.26 R50.1@1124.5,2439 1170,2439 v3(1171,2440) ; R33.1@1437,1682.14 v1(1482.5,1682.14) ; L1.2@1474.42,575.8 1474.87,575.35 v3(1561,575.35) ; L1.3@1474.42,910.45 1474.87,910 v3(1561,910) ; v1(1506,1765.39) C52.1@1506,1810.88
  Bottom Layer w20: v1(1179,2274) 1228.01,2274 C76.2@1228.5,2274.49 ; v1(1189,2351) 1245.52,2351 C77.2@1246.01,2351.49 ; C73.2@1553,2772.76 v1(1599.24,2772.76)
  other v1: 1596.77,2292.76
  other v2: 479.58,1237.72 1219,1256.29 442.18,1260.36 516.98,1260.36 479.58,1283 1166.83,1308.46 1271.17,1308.46 1219,1360.62 1413.38,2515.28 1460.62,2515.28 1437,2533 1413.38,2550.72 1460.62,2550.72
MSB: R34.1 R35.2 U9.14 | length 215.8
  Top Layer w15: R34.1@351.5,2506.76 352,2506.76 R35.2@414.5,2444.26 444,2444.26 483.88,2484.14 U9.14@524.86,2484.14
N13V: C18.1 C19.2 C42.1 C44.2 C62.1 C64.2 C73.1 C74.2 N13V.1 R13.2 U2.6 U5.4 U8.4 U10.6 | length 684.8
  Top Layer w8: U2.6@518.95,1315.48 518.95,1323.37 528.58,1333 548.08,1333 R13.2@585.08,1370
  Top Layer w15: C19.2@650.08,1440 v1(697.58,1440) ; 798.67,1764.3 U5.4@798.67,1794.11 ; U8.4@912.61,2610.62 912.61,2656 ; U10.6@1449.8,2620.6 1449.8,2665.78 1452.5,2668.49 v1(1454.5,2668.49)
  Top Layer w25: v1(749.86,1667.5) C42.1@797.5,1667.5 C44.2@797.5,1732.5 797.5,1763.13 ; C62.1@828,2691.26 892,2691.26 C64.2@893.88,2689.38 ; v1(834,2645) C62.1@834,2691.5 ; C64.2@896,2691.5 912.61,2674.89 912.61,2656
  Bottom Layer w15: v1(1454.5,2668.49) 1454.5,2670.49 1490.01,2705.99 C74.2@1490.01,2712.76 C73.1@1490.01,2772.76
N15V_EXT: D2.2 D5.2 N15V.1 R11.2 | length 515.8
  Top Layer w30: D2.2@345.9,606.2 396.2,606.2 532,742 N15V.1@532,800.26 532,933.46 D5.2@532.8,934.26 532.8,1014.7 R11.2@532.5,1015
NetC1_1: C1.1 R1.1 U1.13 U1.15 U1.16 | length 154.1
  Top Layer w10: v1(1090,1245.26) 1102.02,1257.28 U1.15@1127.46,1257.28 ; v1(1090,1316.26) 1097.8,1308.46 U1.13@1127.46,1308.46
  Bottom Layer w25: v1(1090,1245.26) v1(1090,1316.26)
NetC5_1: C5.1 U1.14 | length 93.1
  Top Layer w8: C5.1@1034.5,1283.26 C5.1@1034.89,1282.87
  Top Layer w10: C5.1@1034.89,1282.87 U1.14@1127.46,1282.87
NetC6_1: C6.1 R4.1 R7.2 U2.9 | length 199.7
  Top Layer w8: U2.9@459.9,1315.48 R4.1@459.9,1356.54
  Top Layer w10: C6.1@376.08,1435.36 379.58,1438.87 R7.2@444.58,1438.87 446.08,1437.37 R4.1@446.08,1370.36 R4.1@459.9,1356.54
NetC8_1: C8.1 C9.1 D3.1 D4.2 R5.2
NetC10_1: C10.1 R6.1 U2.1 U2.2
NetC11_1: C11.1 U3.10 | length 124.7
  Top Layer w8: U3.10@1213.7,346.1 C11.1@1316.66,346.1
  Top Layer w10: C11.1@1316.66,346.1 C11.1@1332,330.76
NetC11_2: C11.2 L1.1 R10.1 U3.11 U3.12
NetC12_1: C12.1 C20.1 R10.2 | length 145.1
  Top Layer w10: C20.1@1392,273.82 C20.1@1392.56,273.26 ; C20.1@1406.5,273.26 1392,287.76 R10.2@1392,328.7 1471.94,328.7 C12.1@1474,330.76
NetC13_1: C13.1 C14.1 C15.1 C16.1 J2.2 R8.1 R9.2 U3.3
NetC15_2: C15.2 C16.2 C17.1 C21.2 C22.2 C23.2 C24.2 D5.1 R14.1 R15.1 U3.1 U3.2 U3.13
  other v2: 1138.9,287.05 1097.56,336.26 1138.9,336.26 1180.24,336.26 1138.9,385.47
NetC17_2: C17.2 U3.7 U3.9 | length 238.2
  Top Layer w8: U3.9@1213.7,326.42 1271.84,326.42 v1(1281,317.26) ; U3.7@1219.21,287.05 1236,270.26
  Top Layer w10: U3.7@1213.7,287.05 U3.7@1219.21,287.05 ; 1236,270.26 v1(1236,252.26) 1236.46,251.8 C17.2@1236.46,216.26
  Bottom Layer w10: v1(1236,252.26) 1281,297.26 v1(1281,317.26)
NetC19_1: C19.1 R13.1 R16.2 U2.7 | length 198.8
  Top Layer w8: U2.7@499.27,1315.48 499.27,1347.18 R13.1@522.09,1370 522.09,1438 R16.2@521.58,1438.5 585.59,1438.5 C19.1@587.09,1440
NetC20_2: C20.2 R12.1 R15.2 U3.8 | length 200.2
  Top Layer w8: U3.8@1213.7,306.73 1255.98,306.73
  Top Layer w10: 1255.98,306.73 R15.2@1288.9,273.82 1289.46,273.26 C20.2@1343.5,273.26 1343.5,225.32 R12.1@1337.44,219.26
NetC21_1: C21.1 U3.6 | length 85.4
  Top Layer w8: 1049,280.26 1055.79,287.05 U3.6@1064.09,287.05
  Top Layer w10: 1049,280.26 1049,224.66 C21.1@1057.4,216.26
NetC25_1: C25.1 R11.1 U2.5
NetC26_2: C26.2 U2.3 | length 55.7
  Top Layer w8: C26.2@464.09,1156 479.58,1171.5 U2.3@479.58,1205.24
NetC27_1: C27.1 R18.1 U5.2 | length 151.2
  Top Layer w15: R18.1@656.99,1868.27 C27.1@724,1868.27 746.97,1845.29 U5.2@798.67,1845.29
NetC27_2: C27.2 R20.1 U5.1 | length 168.3
  Top Layer w15: R20.1@655.5,1931.64 655.88,1931.26 C27.2@724,1931.26 784.38,1870.88 U5.1@798.67,1870.88
NetC28_1: C28.1 C32.1 C40.1 C41.1 R17.1 R25.2 U5.6 | length 405.9
  Top Layer w15: U5.6@973.86,1819.7 1039.9,1819.7 C28.1@1047,1812.6 C40.1@1047,1745.13 C41.1@1113,1745.13 R25.2@1177,1745.13 ; C28.1@1048.5,1814.09 C32.1@1112.5,1814.09 ; C32.1@1111.77,1812.6 1113.27,1814.09 R17.1@1179.5,1814.09
NetC28_2: C28.2 C32.2 R22.1 U5.7 | length 218.4
  Top Layer w15: U5.7@973.86,1845.29 1016.7,1845.29 C28.2@1047,1875.59 C32.2@1111.77,1875.59 1179,1875.59 R22.1@1179.5,1876.09
NetC33_1: C33.1 L2.1 U4.2 | length 139.2
  Top Layer w15: L2.1@144,1824.64 144.65,1823.99 C33.1@219,1823.99 222.7,1820.29 U4.2@281.4,1820.29
NetC34_1: C34.1 U4.5 | length 102.5
  Top Layer w15: C34.1@400.5,1707.5 400.5,1743.13 426.47,1769.11 U4.5@456.6,1769.11
NetC35_2: C35.2 R19.1 | length 67
  Top Layer w20: C35.2@529,1663.99 R19.1@529,1731
NetC38_1: C38.1 C39.1 R24.2 U5.3 | length 210.3
  Top Layer w15: R24.2@599,1793.99 C38.1@666.27,1793.99 C39.1@726.27,1793.99 751.97,1819.7 U5.3@798.67,1819.7
NetC59_1: C59.1 R36.2 R38.1 U10.5 | length 257.1
  Top Layer w15: C59.1@1465.5,2740.99 R36.2@1465.5,2792 ; C59.1@1470.94,2734.55 1483,2722.49 1483,2658.27 1475.39,2650.66 U10.5@1475.39,2620.6 1522.05,2620.6 R38.1@1548.45,2647
NetC59_2: C59.2 R42.2 U10.8 | length 233.2
  Top Layer w15: R42.2@1333,2562.76 1370.77,2562.76 1398.61,2590.6 U10.8@1398.61,2620.6 1398.61,2645.67 1380.5,2663.78 1380.5,2708 C59.2@1402.5,2730
NetC65_2: C65.2 U8.2 U9.3 | length 380.9
  Top Layer w15: U9.3@757.14,2484.14 858.14,2484.14 907.63,2533.63 946.58,2533.63 963.8,2550.84 U8.2@963.8,2610.62 963.8,2695.55 C65.2@965,2696.76 C65.2@965.15,2696.6
NetC66_1: C66.1 J6.1 R38.2 R44.2 VCNTLP.1 | length 847.3
  Top Layer w15: J6.1@1595,2974 VCNTLP.1@1822,2974 1913,2883 C66.1@1913,2633.27 1847.73,2633.27 1830,2651 R44.2@1830,2692.09 1753.64,2692.09 R38.2@1729.55,2668
NetC66_2: C66.2 C69.1 C70.1 R44.1 R46.2
NetC67_2: C67.2 U8.6 U9.6 | length 450.7
  Top Layer w15: v1(710,2561.26) 757.49,2561.26 U9.6@757.14,2560.91 ; C67.2@912,2349.76 912,2361 938.2,2387.2 U8.6@938.2,2435.42 938.2,2474.68 936,2476.89 v1@936,2478.6 ; v1(936,2480.76) v1@936,2478.6 ; v1@936.42,2478.18 v1@936,2478.6
  Bottom Layer w15: v1(710,2561.26) 790.5,2480.76 v1(936,2480.76)
NetC68_1: C68.1 R36.1 R41.2 R42.1 | length 475.9
  Top Layer w15: R41.2@1133,2562.76 1270.01,2562.76 1270.01,2752.99 1309.01,2792 R36.1@1402.5,2792
NetC68_2: C68.2 R47.2 R48.1 R51.1 | length 477.4
  Top Layer w15: R47.2@1133,2502.76 1134.5,2501.26 1268.51,2501.26 1270.01,2502.76 1270.01,2316.99 1317.99,2269 R51.1@1403.5,2269
NetC70_2: C70.2 J7.1 R46.1 R49.2 VCNTLM.1 | length 829.4
  Top Layer w15: R49.2@1729.55,2419 1729.55,2385.45 1736.09,2378.91 R46.1@1830,2378.91 1830,2425 1844.5,2439.5 C70.2@1913,2439.5 1913,2279 VCNTLM.1@1792,2158 J7.1@1792,1932
NetC75_1: C75.1 R49.1 R51.2 U10.4 | length 270.8
  Top Layer w15: R51.2@1466.5,2269 1466,2269.5 C75.1@1466,2331.49 1483,2348.49 1483,2404.71 1475.39,2412.32 U10.4@1475.39,2445.4 1522.05,2445.4 R49.1@1548.45,2419
NetC75_2: C75.2 R48.2 U10.1 | length 239.9
  Top Layer w15: R48.2@1333,2502.76 1334.76,2501 R48.2@1339.5,2501 1375,2501 1398.61,2477.39 U10.1@1398.61,2445.4 1398.61,2417.31 1387,2405.7 1387,2347.5 1394.5,2339.99 C75.2@1394.5,2321.49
